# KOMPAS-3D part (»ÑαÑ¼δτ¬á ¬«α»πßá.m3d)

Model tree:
1. Эскиз:1
2. Операция выдавливания:1
     Расстояние 1 = 64; Расстояние 2 = 64
3. Эскиз:2
4. Вырезать элемент выдавливания:1
     Расстояние 2 = 64; Расстояние 1 = 64
5. Эскиз:3
6. Операция выдавливания:2
     Расстояние 1 = 0.2; Расстояние 2 = 1.1
7. Эскиз:4
8. Операция выдавливания:3
     Расстояние 1 = 2; Расстояние 2 = 1.1
9. Эскиз:5
10. Операция выдавливания:4
     Расстояние 1 = 1; Расстояние 2 = 1.1

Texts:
  Сплав АЛ8  ГОСТ 1583-93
